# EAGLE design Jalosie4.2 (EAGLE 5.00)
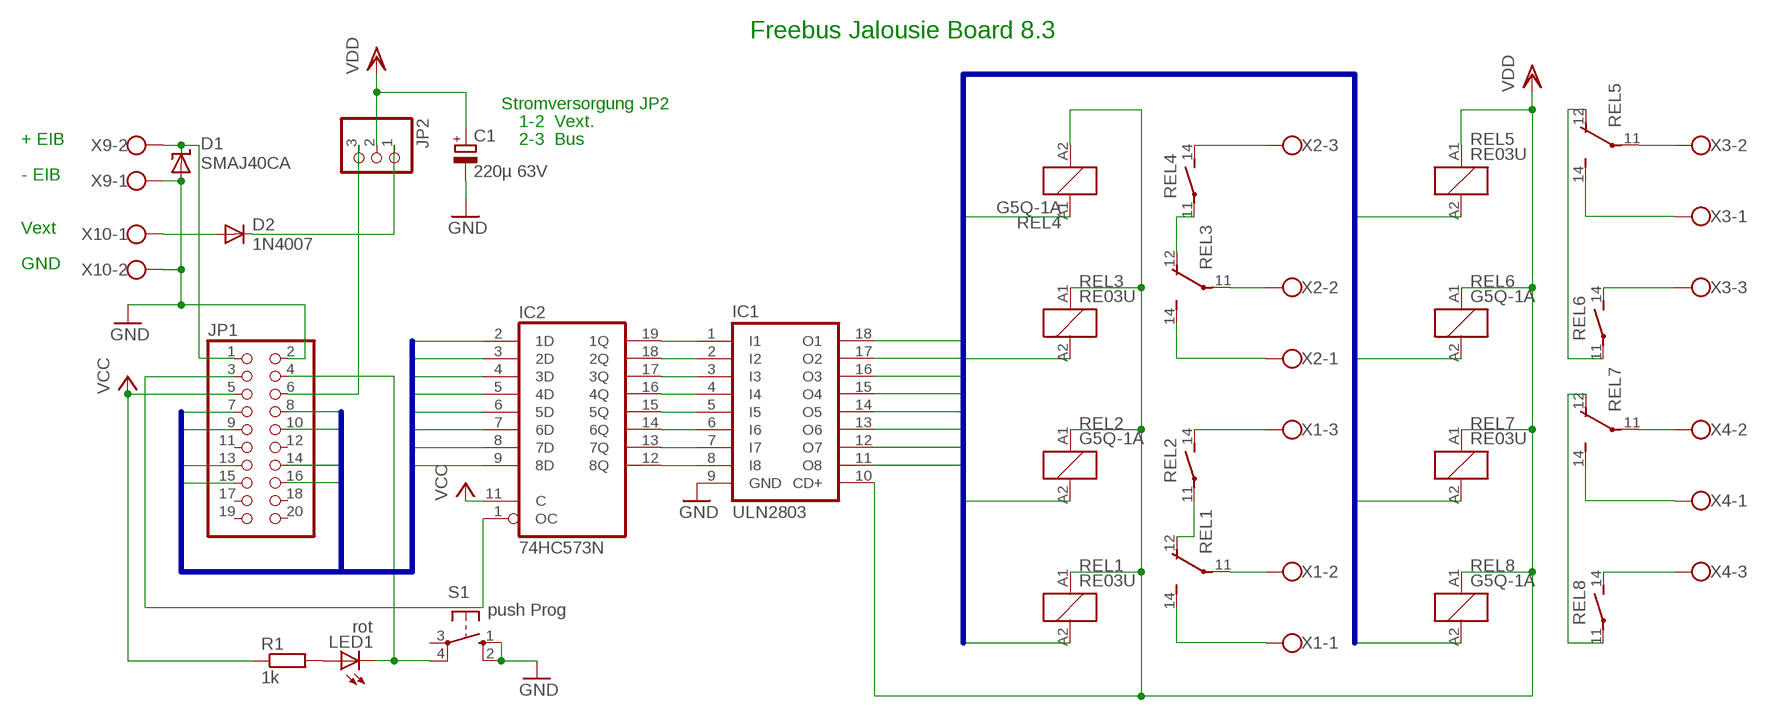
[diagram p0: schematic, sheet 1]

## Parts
C1  220µ 63V  CPOL-EUTT5D10  [TT5D10]
D1  SMAJ40CA  SUPPRESSOR-SMBJ  [SMBJ]
D2  1N4007  1N4004  [DO41-10]
IC1  ULN2803  ULN2803A  [DIL18]
IC2  74HC573N  [DIL20]
JP1  PINHD-2X10  [2X10]
JP2  PINHD-1X3  [1X03]
LED1  rot  LED3MM  [LED3MM]
R1  1k  R-EU_0204/7  [0204/7]
REL1  RE03U  [G5Q_1_EU]
REL2  G5Q-1A  RE030024  [RE-SCHRACK]
REL3  RE03U  [G5Q_1_EU]
REL4  G5Q-1A  RE030024  [RE-SCHRACK]
REL5  RE03U  [G5Q_1_EU]
REL6  G5Q-1A  RE030024  [RE-SCHRACK]
REL7  RE03U  [G5Q_1_EU]
REL8  G5Q-1A  RE030024  [RE-SCHRACK]
S1  push Prog  10-XX  [B3F-10XX]
X1  W237-03P  [W237-133]
X2  W237-03P  [W237-133]
X3  W237-03P  [W237-133]
X4  W237-03P  [W237-133]
X9  W237-102  [W237-102]
X10  W237-102  [W237-102]

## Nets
GND: C1.- D1.A IC1.9(GND) JP1.2 S1.1(S) S1.2(S1) X9.1 X10.2
IO1: IC2.2(1D) JP1.16
IO2: IC2.3(2D) JP1.15
IO3: IC2.4(3D) JP1.14
IO4: IC2.5(4D) JP1.13
IO5: IC2.6(5D) JP1.10
IO6: IC2.7(6D) JP1.9
IO7: IC2.8(7D) JP1.8
IO8: IC2.9(8D) JP1.7
N$1: REL3.12(14:O) REL4.11(2:P)
N$2: REL4.14(2:S) X2.3
N$3: REL1.12(14:O) REL2.11(2:P)
N$4: REL1.11(14:P) X1.2
N$5: REL3.11(14:P) X2.2
N$6: REL2.14(2:S) X1.3
N$7: REL7.11(14:P) X4.2
N$8: REL5.11(14:P) X3.2
N$9: REL1.14(14:S) X1.1
N$10: REL5.12(14:O) REL6.11(2:P)
N$11: JP1.4 LED1.K(C) S1.4(P1)
N$12: LED1.A R1.2
N$13: REL3.14(14:S) X2.1
N$14: REL6.14(2:S) X3.3
N$15: REL8.14(2:S) X4.3
N$16: REL7.14(14:S) X4.1
N$17: D2.A X10.1
N$18: JP1.6 JP2.3
N$19: REL5.14(14:S) X3.1
N$20: D1.C JP1.1 X9.2
N$21: IC1.1(I1) IC2.19(1Q)
N$22: IC1.2(I2) IC2.18(2Q)
N$23: IC1.3(I3) IC2.17(3Q)
N$24: IC1.4(I4) IC2.16(4Q)
N$25: IC1.5(I5) IC2.15(5Q)
N$27: IC1.6(I6) IC2.14(6Q)
N$28: IC1.7(I7) IC2.13(7Q)
N$29: IC1.8(I8) IC2.12(8Q)
N$30: REL7.12(14:O) REL8.11(2:P)
N$31: D2.C JP2.1
N$33: IC2.1(OC) JP1.3
R1: IC1.14(O5) REL4.A1
R2: IC1.13(O6) REL3.A2
R3: IC1.12(O7) REL2.A2
R4: IC1.11(O8) REL1.A2
R5: IC1.15(O4) REL5.A2
R6: IC1.16(O3) REL6.A2
R7: IC1.17(O2) REL7.A2
R8: IC1.18(O1) REL8.A2
VCC: IC2.11(C) JP1.5 R1.1
VDD: C1.+ IC1.10(CD+) JP2.2 REL1.A1 REL2.A1 REL3.A1 REL4.A2 REL5.A1 REL6.A1 REL7.A1 REL8.A1
Unconnected: JP1.11 JP1.12 JP1.17 JP1.18 JP1.19 JP1.20 S1.3(P)

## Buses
R[1..8]
IO[1..8]

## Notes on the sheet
- Freebus Jalousie Board 8.3
- Stromversorgung JP2
- 1-2  Vext.
- + EIB | 2-3  Bus
- - EIB
- Vext
- GND

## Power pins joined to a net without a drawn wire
GND: IC2.10(GND)
VCC: IC2.20(VCC)

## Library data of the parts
C1 = rcl:CPOL-EU: POLARIZED CAPACITOR, European symbol
D1 = diode:SUPPRESSOR-: Suppressor diode
D2 = diode:1N4004: DIODE
IC1 = uln-udn:ULN2803A: DRIVER ARRAY
IC2 = 74xx-eu:74*573: 8-bit D latch BUS DRIVER
JP1 = pinhead:PINHD-2X10: PIN HEADER
JP2 = pinhead:PINHD-1X3: PIN HEADER
LED1 = led:LED: LED
R1 = rcl:R-EU_: RESISTOR, European symbol
REL1 REL3 REL5 REL7 = freebus_relay:RE03U
REL2 REL4 REL6 REL8 = relay:RE03*: Miniature PCB Relay 1 pole 6 A SCHRACK Source: http://www.schrack.com/.. 5812.pdf
S1 = switch-omron:10-XX: OMRON SWITCH
X1-X4 = con-wago-508:W237-03P: WAGO SREW CLAMP
X9 X10 = con-wago-500:W237-102: WAGO SCREW CLAMP

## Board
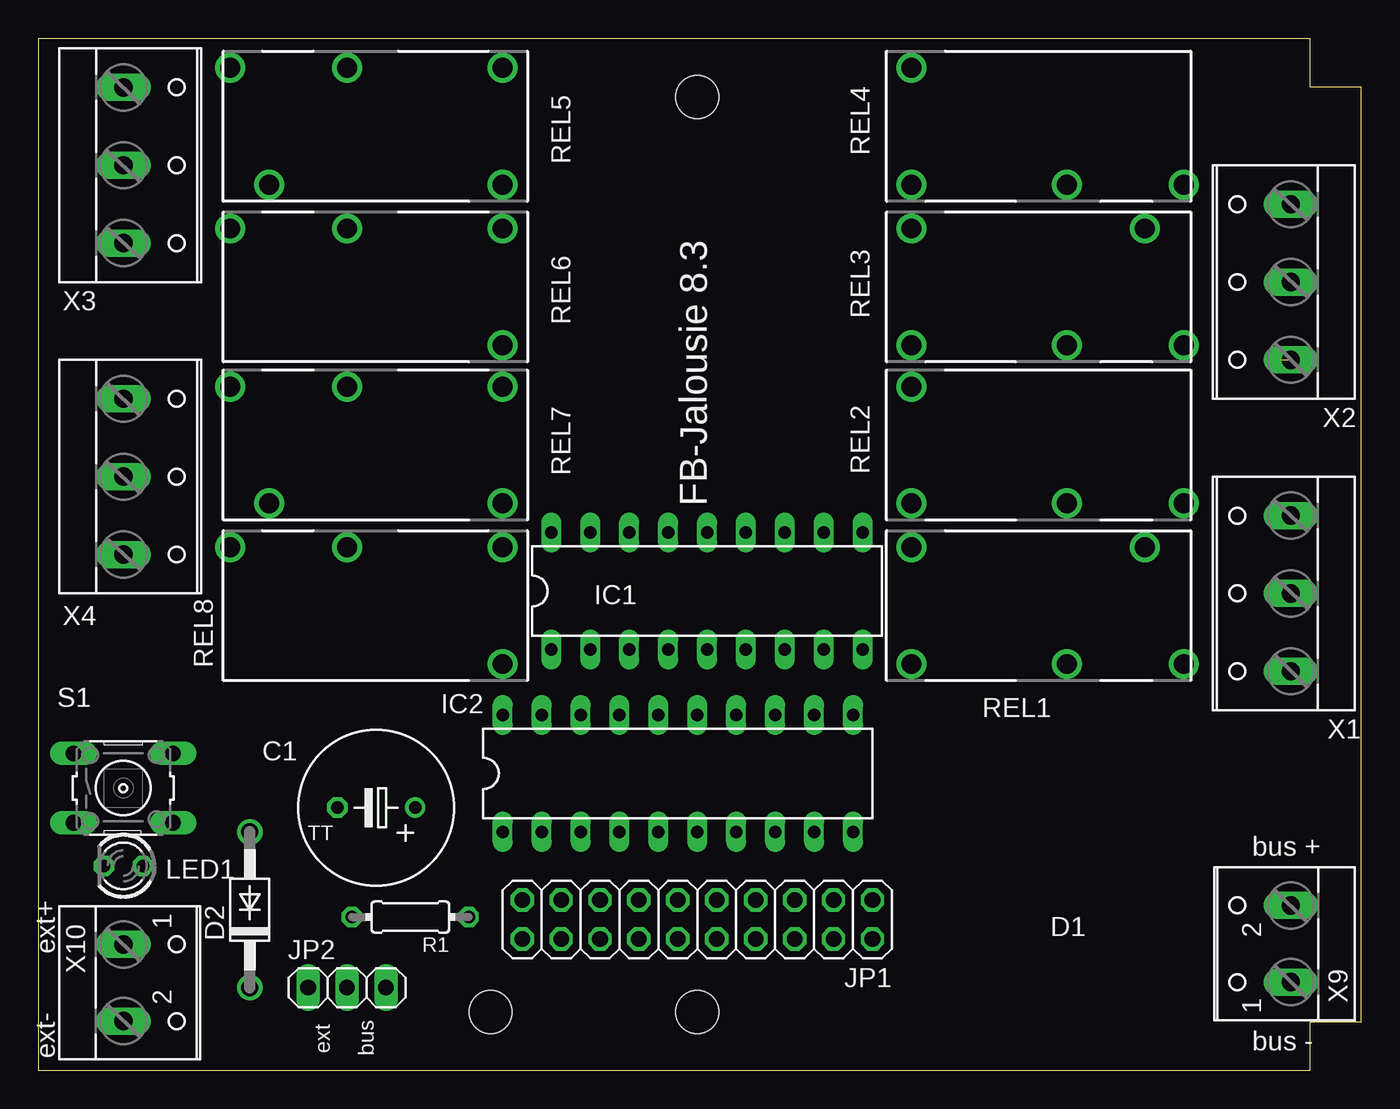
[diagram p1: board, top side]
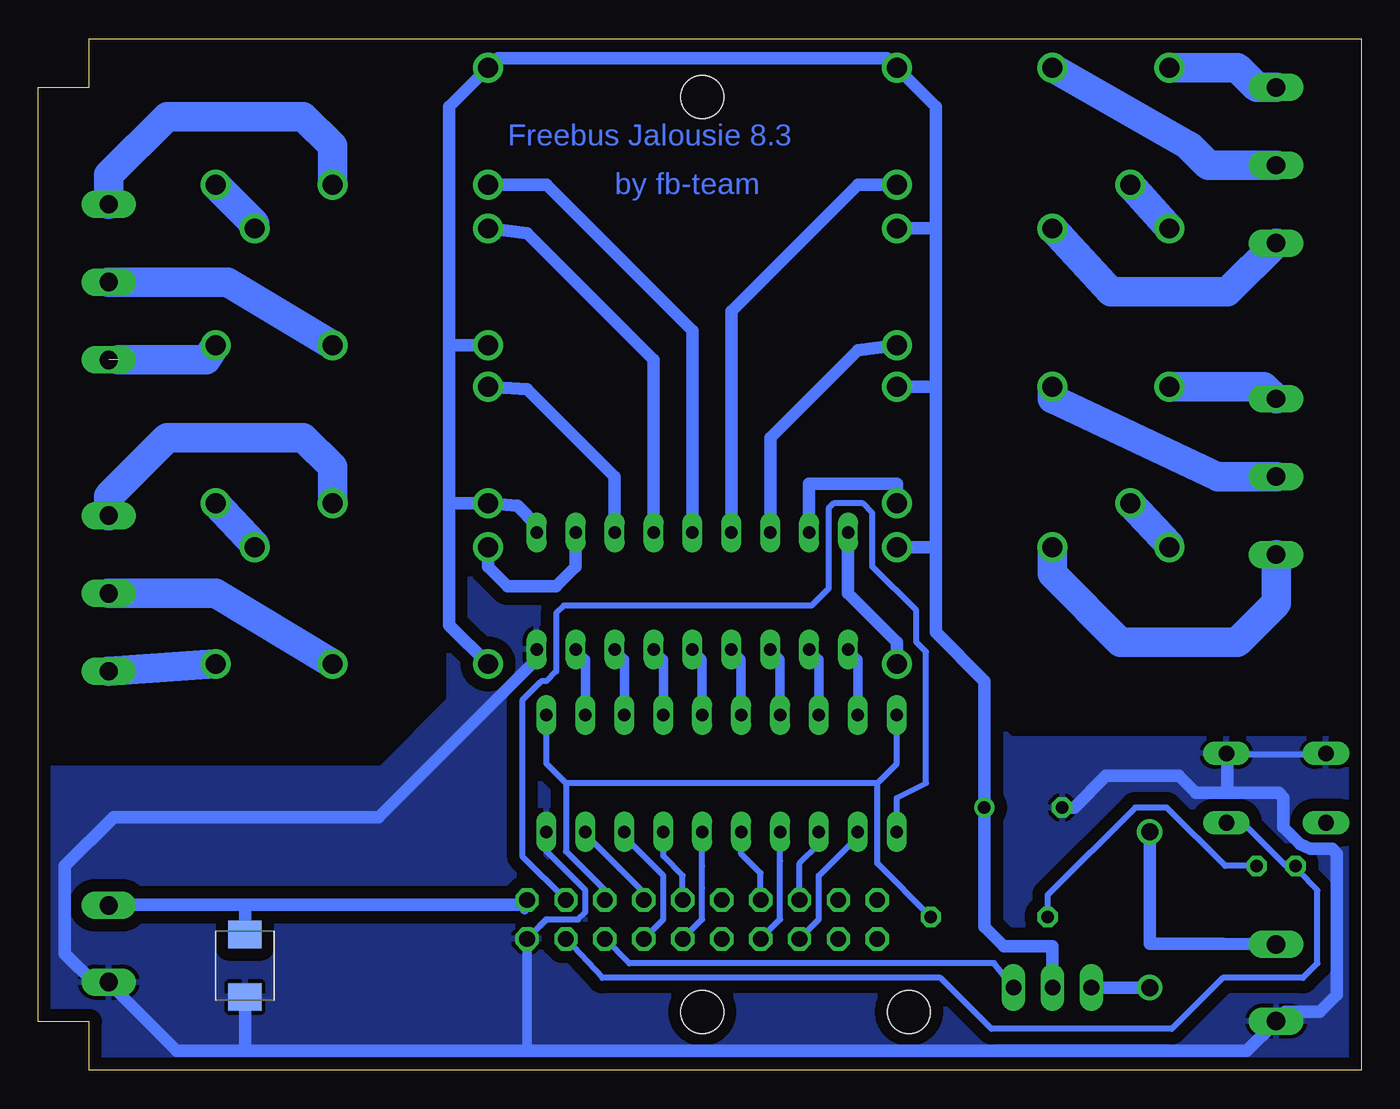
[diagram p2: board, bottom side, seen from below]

Size 86.35 x 67.31 mm. Coordinates in mm from the lower left corner, seen from the top.
Outline: 0,0.01 83.02,0 83.02,3.18 86.35,3.18 86.35,64.13 83.02,64.13 83.02,67.31 0,67.31 0,0.01
Copper layers (1*16): Top 0.035mm / dielectric 1.5mm / Bottom 0.035mm
Design rules "default *": minimum track width 10mil, minimum drill 24mil, track to track 16mil, track to pad 16mil, pad to pad 16mil, via to via 16mil, smd to smd 8mil, copper to edge 20mil, drill to drill 10mil, minimum pad ring 10mil, minimum via ring 8mil, stop-mask expansion 4mil, vias tented up to drill 0mil, thermal gap 10mil
Holes 2.8 mm at 43.02,3.81 43.02,63.5 29.52,3.81

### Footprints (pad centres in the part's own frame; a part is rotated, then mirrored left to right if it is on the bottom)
TT5D10 = drill 0.813 round: + -2.54,0 | drill 0.813 octagon: - 2.54,0
SMBJ = smd 1.78 x 2.16: A 2.04,0; C -2.03,0
DO41-10 = drill 1.118 round: A 5.08,0; C -5.08,0
DIL18 = drill 0.813 long: 1 -10.16,-3.81; 2 -7.62,-3.81; 3 -5.08,-3.81; 4 -2.54,-3.81; 5 0,-3.81; 6 2.54,-3.81; 7 5.08,-3.81; 8 7.62,-3.81; 9 10.16,-3.81; 10 10.16,3.81; 11 7.62,3.81; 12 5.08,3.81; 13 2.54,3.81; 14 0,3.81; 15 -2.54,3.81; 16 -5.08,3.81; 17 -7.62,3.81; 18 -10.16,3.81
DIL20 = drill 0.813 long: 1 -11.43,-3.81; 2 -8.89,-3.81; 3 -6.35,-3.81; 4 -3.81,-3.81; 5 -1.27,-3.81; 6 1.27,-3.81; 7 3.81,-3.81; 8 6.35,-3.81; 9 8.89,-3.81; 10 11.43,-3.81; 11 11.43,3.81; 12 8.89,3.81; 13 6.35,3.81; 14 3.81,3.81; 15 1.27,3.81; 16 -1.27,3.81; 17 -3.81,3.81; 18 -6.35,3.81; 19 -8.89,3.81; 20 -11.43,3.81
2X10 = drill 1.016 octagon: 1 -11.43,-1.27; 2 -11.43,1.27; 3 -8.89,-1.27; 4 -8.89,1.27; 5 -6.35,-1.27; 6 -6.35,1.27; 7 -3.81,-1.27; 8 -3.81,1.27; 9 -1.27,-1.27; 10 -1.27,1.27; 11 1.27,-1.27; 12 1.27,1.27; 13 3.81,-1.27; 14 3.81,1.27; 15 6.35,-1.27; 16 6.35,1.27; 17 8.89,-1.27; 18 8.89,1.27; 19 11.43,-1.27; 20 11.43,1.27
1X03 = drill 1.016 long: 1 -2.54,0; 2 0,0; 3 2.54,0
LED3MM = drill 0.813 octagon: A -1.27,0; K 1.27,0
0204/7 = drill 0.813 octagon: 1 -3.81,0; 2 3.81,0
G5Q_1_EU = drill 1.3 round: 11 1.27,-3.81; 12 6.35,3.81; 14 8.89,-3.81; A1 -8.89,-3.81; A2 -8.89,3.81
RE-SCHRACK = drill 1.3 round: 11 8.89,-3.81; 14 1.27,-3.81; A1 -8.89,-3.81; A2 -8.89,3.81
B3F-10XX = drill 1.016 long: 1 -3.251,2.261; 2 3.251,2.261; 3 -3.251,-2.261; 4 3.251,-2.261
W237-133 = drill 1.194 long: 1 -5.08,-0.635; 2 0,-0.635; 3 5.08,-0.635
W237-102 = drill 1.194 long: 1 -2.5,-1.27; 2 2.5,-1.27

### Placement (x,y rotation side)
C1  22.06,17.14 180 top
D1  72.86,6.83 270 bottom
D2  13.8,10.48 90 top
IC1  43.65,31.27 0 top
IC2  41.75,19.37 0 top
JP1  43.02,9.84 180 top
JP2  20.16,5.4 0 top
LED1  5.55,13.34 180 top
R1  24.28,10 180 top
REL1  65.88,30.32 0 top
REL2  65.88,40.8 0 top
REL3  65.88,51.12 0 top
REL4  65.88,61.6 0 top
REL5  21.43,61.6 180 top
REL6  21.43,51.12 180 top
REL7  21.43,40.8 180 top
REL8  21.43,30.32 180 top
S1  5.55,18.41 0 top
X1  81.12,31.11 90 top
X2  81.12,51.44 90 top
X3  6.18,59.05 270 top
X4  6.18,38.73 270 top
X9  80.48,8.26 90 top
X10  6.82,5.71 270 top

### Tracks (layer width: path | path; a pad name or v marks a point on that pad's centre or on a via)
GND
  Bottom 0.406: 53.81,26.83 IC1.9 | JP1.2 53.18,9.84 51.11,9.84 50.64,10.32 50.64,11.75 53.18,14.29 IC2.10 | S1.2 8.76,20.64 2.34,20.64 S1.1
  Bottom 0.61: 81.75,5.72 X9.1 | 54.45,1.27 JP1.2
  Bottom 0.813: 72.86,1.27 54.45,1.27 7.46,1.27 5.55,3.18 X10.2 4.96,3.81 2.69,3.81 1.58,4.92 1.58,14.13 1.9,14.45 3.33,14.45 3.96,14.76 5.07,15.88 5.07,17.78 5.39,18.1 8.73,18.1 | 72.86,1.27 77.31,1.27 81.75,5.72 82.7,5.72 84.61,7.62 84.61,13.34 81.43,16.51 64.13,16.51 53.81,26.83 | 72.86,1.27 D1.A | 8.73,18.1 10.79,18.1 10.79,18.12 11.92,19.21 16.66,19.21 18.73,17.15 C1.- | S1.2 8.73,20.6 8.73,18.1
  pour Bottom (isolate 0.813): 0.47,0.64 0.47,20.95 1.1,21.59 22.85,21.59 27.62,26.35 27.62,27.3 27.77,62.87 30.95,66.04 56.35,66.04 59.53,62.87 59.53,24.13 63.97,19.68 86.04,19.68 86.04,0.64
IO1
  Bottom 0.406: JP1.16 35.4,9.84 35.4,12.7 32.86,15.24 IC2.2
IO2
  Bottom 0.406: IC2.3 35.4,14.76 36.67,13.49 JP1.15
IO3
  Bottom 0.406: IC2.4 37.94,13.65 37.94,9.84 JP1.14
IO4
  Bottom 0.406: IC2.5 40.48,14.13 39.21,12.86 39.21,10.8 39.36,10.64 JP1.13
IO5
  Bottom 0.406: IC2.6 43.02,13.34 43.02,11.91 43.02,9.84 JP1.10
IO6
  Bottom 0.406: IC2.7 45.56,13.97 44.29,12.7 JP1.9
IO7
  Bottom 0.406: IC2.8 48.1,15.24 45.56,12.7 45.56,9.84 JP1.8
IO8
  Bottom 0.406: IC2.9 50.64,15.4 48.41,13.18 46.83,11.59 JP1.7
N$1
  Bottom 1.93: REL4.11 72.23,55.25 REL3.12
N$2
  Bottom 1.93: REL4.14 67.15,60.33 69.05,62.23 77.94,62.23 81.75,58.42 X2.3
N$3
  Bottom 1.93: REL1.12 72.23,34.29 REL2.11
N$4
  Bottom 1.93: X1.2 74.77,31.12 REL1.11
N$5
  Bottom 1.93: REL3.11 73.97,51.44 X2.2
N$6
  Bottom 1.93: REL2.14 67.15,39.37 69.05,41.28 77.94,41.28 81.75,37.47 X1.3
N$7
  Bottom 1.93: X4.2 9.36,38.74 20.16,43.82 REL7.11
N$8
  Bottom 1.93: X3.2 10,59.06 11.27,60.33 REL5.11
N$9
  Bottom 1.93: REL1.14 X1.1
N$10
  Bottom 1.93: REL6.11 REL5.12
N$11
  Bottom 0.406: JP1.4 49.52,6.03 27.46,6.03 24.12,2.7 12.38,2.7 9.04,6.03 3.8,6.03 2.85,6.99 2.85,11.75 4.12,13.02 4.92,13.34 | 4.92,13.34 LED1.K | S1.4 8.76,16.19 7.77,16.19 4.92,13.34
N$12
  Bottom 0.406: R1.2 20.47,11.43 14.76,17.15 12.69,17.15 8.88,13.34 LED1.A
N$13  (1 unrouted)
  Bottom 1.93: REL3.14 75.4,46.36 81.12,46.36
N$14
  Bottom 1.93: X3.3 8.73,50.8 16.35,50.8 REL6.14
N$15
  Bottom 1.93: X4.3 5.55,30.48 8.09,27.94 15.71,27.94 20.16,32.39 REL8.14
N$16
  Bottom 1.93: X4.1 6.34,44.61 REL7.14
N$17
  Bottom 0.813: X10.1 9.04,8.26 13.81,8.26 D2.A
N$18
  Bottom 0.406: JP2.3 23.97,6.99 47.78,6.99 | 47.78,6.99 | 47.78,6.99 JP1.6
N$19
  Bottom 1.93: X3.1 6.82,64.14 8.09,65.41 REL5.14
N$20
  Bottom 0.254: X9.2 81.75,10.8
  Bottom 0.61: 80.44,10.76 80.48,10.76 80.48,10.8 | 54.76,10.8 54.6,10.48 JP1.1
  Bottom 0.813: 80.48,10.76 X9.2 | 54.76,10.8 72.86,10.8 | 72.86,10.8 80.48,10.8 | 72.86,10.8 D1.C
N$21
  Bottom 0.61: IC2.19 | IC1.1 32.86,26.83 IC2.19
N$22
  Bottom 0.61: IC2.18 | IC1.2 35.4,26.83 IC2.18
N$23
  Bottom 0.61: IC2.17 | IC1.3 37.94,26.83 IC2.17
N$24
  Bottom 0.61: IC2.16 | IC1.4 40.48,26.83 IC2.16
N$25
  Bottom 0.61: IC2.15 | IC1.5 43.02,26.83 IC2.15
N$27
  Bottom 0.61: IC2.14 | IC1.6 45.56,26.83 IC2.14
N$28
  Bottom 0.61: IC2.13 | IC1.7 48.1,26.83 IC2.13
N$29
  Bottom 0.61: IC2.12 | IC1.8 50.64,26.83 IC2.12
N$30
  Bottom 1.93: REL8.11 12.54,34.29 REL7.12
N$31
  Bottom 0.813: D2.C JP2.1
N$33
  Bottom 0.406: JP1.3 54.76,13.97 54.76,24.13 53.65,25.24 53.49,25.4 53.18,25.4 52.54,26.04 52.54,29.85 52.06,30.32 35.87,30.32 34.76,31.43 34.76,36.67 34.44,36.99 32.54,36.99 31.9,36.35 31.9,32.86 29.05,30 29.05,27.94 28.41,27.31 28.41,18.73 30.32,17.78 IC2.1
R1
  Bottom 0.813: REL4.A1 53.18,57.79 43.65,48.26 IC1.14
R2
  Bottom 0.813: IC1.13 46.19,46.36 54.45,54.61 REL3.A2
R3
  Bottom 0.813: REL2.A2 54.45,44.45 48.73,38.74 IC1.12
R4
  Bottom 0.813: IC1.11 51.27,32.86 52.54,31.59 55.72,31.59 56.99,32.86 REL1.A2
R5
  Bottom 0.813: IC1.15 41.11,49.53 32.86,57.79 REL5.A2
R6
  Bottom 0.813: REL6.A2 32.86,46.99 38.57,41.28 IC1.16
R7
  Bottom 0.813: IC1.17 36.03,38.26 30.32,38.26 REL7.A2
R8
  Bottom 0.813: REL8.A2 30.32,27.94 33.49,31.12 IC1.18
VCC
  Bottom 0.406: IC2.20 30.32,20 31.59,18.73 | 31.59,18.73 51.91,18.73 | 51.91,18.73 53.18,20 IC2.11 | JP1.5 49.37,11.75 51.91,14.29 51.91,18.73 | 31.59,18.73 | R1.1 31.59,13.49 31.59,18.73
VDD
  Bottom 0.813: 27.78,34.13 REL8.A1 | 27.78,34.13 27.78,44.61 | 27.78,44.61 27.78,54.93 | 27.78,54.93 REL6.A1 | 27.78,54.93 27.78,62.87 REL5.A1 30.95,66.04 56.35,66.04 REL4.A2 59.53,62.87 59.53,47.31 | 59.53,47.31 59.53,36.99 | 59.53,36.99 59.53,29.05 REL1.A1 | 59.53,36.99 REL2.A1 55.08,36.83 53.81,35.56 IC1.10 | 27.78,44.61 REL7.A1 | 59.53,47.31 REL3.A1 | JP2.2 20.16,8.1 23.33,8.1 24.6,9.37 C1.+ 24.6,25.4 27.78,28.58 27.78,34.13

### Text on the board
Bottom: Freebus Jalousie 8.3 | by fb-team
tPlace: FB-Jalousie 8.3 | bus + | ext+ | ext- | ext | bus | bus -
